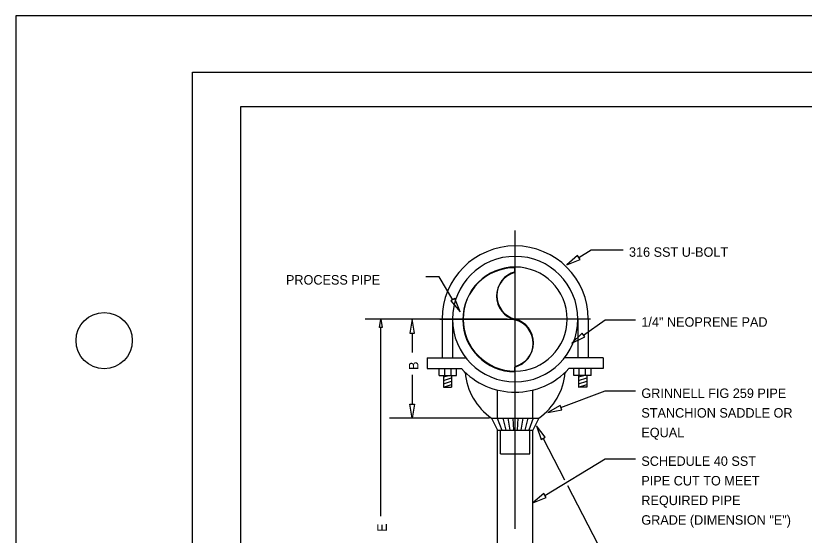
# Model space of a CAD drawing. Extents: x 2147138 to 2147698, y 2147153 to 2147515.
# Drawn here: x 2147137.8 to 2147237.7, y 2147449.2 to 2147515.1 of the extents above; entities that cross this region are included whole.
import ezdxf

# ---------------------------------------------------------------- set-up
doc = ezdxf.new("R2010")
doc.units = 0
for name, color, linetype in [('1', 7, 'Continuous'), ('CONSTRUCTION_CLASS', 7, 'Continuous'), ('G-DETL-ANNO-LW10', 7, 'Continuous'), ('G-DETL-CNTR', 7, 'Continuous'), ('G-DETL-HIDD', 7, 'Continuous'), ('G-DETL-LW10', 7, 'Continuous'), ('G-DETL-PATT', 7, 'Continuous'), ('PATTERN_CLASS', 7, 'Continuous')]:
    doc.layers.add(name, color=color, linetype=linetype)

msp = doc.modelspace()

# ---------------------------------------------------------------- linework, layer by layer
at = {"layer": '1'}
msp.add_line((2147201.099, 2147482.637), (2147201.099, 2147483.237), dxfattribs=at)
at = {"layer": 'CONSTRUCTION_CLASS'}
for p, q in [((2147697.658, 2147515.078), (2147137.785, 2147515.078)), ((2147137.785, 2147515.078), (2147137.785, 2147152.807)), ((2147160.204, 2147507.94), (2147689.056, 2147507.94)), ((2147160.204, 2147160.521), (2147160.204, 2147507.94)), ((2147160.204, 2147507.94), (2147160.204, 2147507.94))]:
    msp.add_line(p, q, dxfattribs=at)
msp.add_circle((2147148.994, 2147473.911), 3.566, dxfattribs=at)
at = {"layer": 'DEFPOINTS'}
for p, q in [((2147201.099, 2147476.637), (2147201.099, 2147476.637)), ((2147198.849, 2147464.074), (2147198.849, 2147464.074))]:
    msp.add_line(p, q, dxfattribs=at)
at = {"layer": 'G-DETL-ANNO-LW10'}
for p, q in [((2147209.173, 2147484.444), (2147210.741, 2147485.424)), ((2147210.741, 2147485.424), (2147214.805, 2147485.424)), ((2147191.481, 2147482.002), (2147189.788, 2147482.002)), ((2147193.202, 2147479.094), (2147191.481, 2147482.002)), ((2147185.7, 2147476.637), (2147182.083, 2147476.637)), ((2147200.099, 2147476.637), (2147185.174, 2147476.637)), ((2147209.759, 2147474.619), (2147212.519, 2147476.56)), ((2147212.519, 2147476.56), (2147216.373, 2147476.56)), ((2147184.06, 2147451.682), (2147184.06, 2147475.583)), ((2147188.054, 2147474.845), (2147188.054, 2147472.399)), ((2147188.054, 2147469.56), (2147188.054, 2147465.866)), ((2147206.912, 2147465.427), (2147212.519, 2147467.53)), ((2147212.519, 2147467.53), (2147216.373, 2147467.53)), ((2147197.849, 2147464.074), (2147185.174, 2147464.074)), ((2147204.651, 2147461.518), (2147207.373, 2147456.272)), ((2147204.881, 2147454.29), (2147212.519, 2147458.929)), ((2147212.519, 2147458.929), (2147216.373, 2147458.929)), ((2147207.743, 2147455.56), (2147212.519, 2147446.356)), ((2147198.849, 2147449.279), (2147198.849, 2147450.771)), ((2147203.349, 2147449.279), (2147203.349, 2147450.771))]:
    msp.add_line(p, q, dxfattribs=at)
for points in [[(2147209.332, 2147484.19), (2147209.015, 2147484.697), (2147207.654, 2147483.494)], [(2147193.459, 2147479.246), (2147192.945, 2147478.942), (2147194.115, 2147477.552)], [(2147183.885, 2147475.583), (2147184.06, 2147476.637), (2147184.236, 2147475.583)], [(2147187.755, 2147474.845), (2147188.353, 2147474.845), (2147188.054, 2147476.637)], [(2147209.931, 2147474.375), (2147209.587, 2147474.863), (2147208.293, 2147473.588)], [(2147187.755, 2147465.866), (2147188.353, 2147465.866), (2147188.054, 2147464.074)], [(2147207.017, 2147465.147), (2147206.808, 2147465.707), (2147205.235, 2147464.798)], [(2147204.386, 2147461.38), (2147204.917, 2147461.655), (2147203.826, 2147463.108)], [(2147205.036, 2147454.035), (2147204.726, 2147454.545), (2147203.349, 2147453.36)]]:
    msp.add_lwpolyline(points, close=True, dxfattribs=at)
at = {"layer": 'G-DETL-CNTR'}
for p, q in [((2147201.099, 2147450.052), (2147201.099, 2147487.863)), ((2147191.558, 2147476.637), (2147201.099, 2147476.637)), ((2147210.64, 2147476.637), (2147201.099, 2147476.637))]:
    msp.add_line(p, q, dxfattribs=at)
at = {"layer": 'G-DETL-HIDD'}
for p, q in [((2147199.224, 2147459.574), (2147199.224, 2147462.574)), ((2147202.974, 2147459.574), (2147202.974, 2147462.574)), ((2147199.224, 2147459.574), (2147202.974, 2147459.574))]:
    msp.add_line(p, q, dxfattribs=at)
at = {"layer": 'G-DETL-LW10'}
for p, q in [((2147191.825, 2147476.637), (2147191.825, 2147471.796)), ((2147193.149, 2147476.637), (2147193.149, 2147471.735)), ((2147209.049, 2147476.637), (2147209.049, 2147471.735)), ((2147210.373, 2147476.637), (2147210.373, 2147471.735)), ((2147189.937, 2147471.735), (2147189.937, 2147470.356)), ((2147189.937, 2147471.735), (2147194.84, 2147471.735)), ((2147212.261, 2147471.735), (2147207.358, 2147471.735)), ((2147212.261, 2147471.735), (2147212.261, 2147470.356)), ((2147189.937, 2147470.356), (2147194.292, 2147470.356)), ((2147191.469, 2147469.504), (2147191.469, 2147470.356)), ((2147192.173, 2147469.504), (2147192.173, 2147470.356)), ((2147192.969, 2147469.504), (2147192.969, 2147470.356)), ((2147193.673, 2147469.504), (2147193.673, 2147470.356)), ((2147212.261, 2147470.356), (2147207.906, 2147470.356)), ((2147208.525, 2147469.504), (2147208.525, 2147470.356)), ((2147209.229, 2147469.504), (2147209.229, 2147470.356)), ((2147210.025, 2147469.504), (2147210.025, 2147470.356)), ((2147210.729, 2147469.504), (2147210.729, 2147470.356)), ((2147191.469, 2147469.504), (2147193.673, 2147469.504)), ((2147192.025, 2147469.301), (2147192.681, 2147469.505)), ((2147192.025, 2147469.504), (2147192.025, 2147468.016)), ((2147192.025, 2147468.872), (2147193.047, 2147469.192)), ((2147193.047, 2147469.504), (2147193.047, 2147468.016)), ((2147210.729, 2147469.504), (2147208.525, 2147469.504)), ((2147209.151, 2147469.301), (2147209.807, 2147469.505)), ((2147209.151, 2147469.504), (2147209.151, 2147468.016)), ((2147209.151, 2147468.872), (2147210.173, 2147469.192)), ((2147210.173, 2147469.504), (2147210.173, 2147468.016)), ((2147192.025, 2147468.444), (2147193.047, 2147468.763)), ((2147192.025, 2147468.016), (2147193.047, 2147468.335)), ((2147209.151, 2147468.444), (2147210.173, 2147468.763)), ((2147209.151, 2147468.016), (2147210.173, 2147468.335)), ((2147192.025, 2147468.016), (2147193.047, 2147468.016)), ((2147198.849, 2147464.074), (2147198.849, 2147467.652)), ((2147203.349, 2147464.074), (2147203.349, 2147467.652)), ((2147210.173, 2147468.016), (2147209.151, 2147468.016)), ((2147198.082, 2147464.074), (2147198.849, 2147462.574)), ((2147198.082, 2147464.074), (2147204.099, 2147464.074)), ((2147198.83, 2147464.074), (2147199.409, 2147462.574)), ((2147199.521, 2147464.074), (2147199.925, 2147462.574)), ((2147200.173, 2147464.074), (2147200.413, 2147462.574)), ((2147200.804, 2147464.074), (2147200.885, 2147462.574)), ((2147201.427, 2147464.074), (2147201.351, 2147462.574)), ((2147202.058, 2147464.074), (2147201.822, 2147462.574)), ((2147202.709, 2147464.074), (2147202.309, 2147462.574)), ((2147203.398, 2147464.074), (2147202.825, 2147462.574)), ((2147204.099, 2147464.074), (2147203.349, 2147462.574)), ((2147198.849, 2147462.574), (2147203.349, 2147462.574)), ((2147198.849, 2147444.832), (2147198.849, 2147462.574)), ((2147203.349, 2147444.832), (2147203.349, 2147462.574))]:
    msp.add_line(p, q, dxfattribs=at)
for centre, radius, start, end in [((2147201.099, 2147476.637), 9.274, 0, 180), ((2147201.099, 2147476.637), 7.95, 0, 180), ((2147201.099, 2147476.637), 6.6, 0, 180), ((2147201.099, 2147476.637), 6.6, 0, 180), ((2147201.099, 2147476.637), 7.95, 180, 360), ((2147201.099, 2147476.637), 6.6, 180, 0), ((2147201.099, 2147476.637), 9.262, 222.69828, 317.30172), ((2147202.623, 2147470.53), 7.883, 184.75423, 234.97861), ((2147199.575, 2147470.53), 7.883, 305.02139, 355.24577)]:
    msp.add_arc(centre, radius, start, end, dxfattribs=at)
at = {"layer": 'G-DETL-PATT'}
for points in [[(2147201.072, 2147482.55), (2147201.072, 2147483.15)], [(2147201.072, 2147469.95), (2147201.072, 2147470.565)]]:
    msp.add_lwpolyline(points, dxfattribs=at)
for centre, radius, start, end in [((2147201.072, 2147476.55), 6.6, 90, 270), ((2147201.841, 2147479.55), 3.097, 104.3818, 255.6182), ((2147201.868, 2147479.637), 3.097, 104.3818, 255.6182), ((2147200.332, 2147473.645), 3.089, 283.20998, 75.6182), ((2147200.304, 2147473.558), 3.089, 284.3818, 75.6182)]:
    msp.add_arc(centre, radius, start, end, dxfattribs=at)
at = {"layer": 'PATTERN_CLASS'}
for p, q in [((2147290.476, 2147503.536), (2147166.29, 2147503.536)), ((2147166.29, 2147503.536), (2147166.29, 2147351.266))]:
    msp.add_line(p, q, dxfattribs=at)

# ---------------------------------------------------------------- texts
at = {"layer": 'G-DETL-ANNO-LW10'}
for s, p in [('316 SST U-BOLT', (2147215.531, 2147484.535)), ('PROCESS PIPE', (2147172.041, 2147481.011)), ('1/4" NEOPRENE PAD', (2147217.099, 2147475.671)), ('GRINNELL FIG 259 PIPE', (2147217.099, 2147466.641)), ('STANCHION SADDLE OR', (2147217.099, 2147464.154)), ('EQUAL', (2147217.099, 2147461.667)), ('SCHEDULE 40 SST', (2147217.099, 2147458.04)), ('PIPE CUT TO MEET', (2147217.099, 2147455.554)), ('REQUIRED PIPE', (2147217.099, 2147453.067)), ('GRADE (DIMENSION "E")', (2147217.099, 2147450.58))]:
    msp.add_text(s, height=1.2, dxfattribs=at).set_placement(p)
for s, p in [('B', (2147188.824, 2147470.186)), ('E', (2147184.835, 2147449.676))]:
    msp.add_text(s, height=1.2, rotation=90, dxfattribs=at).set_placement(p)

doc.saveas('drawing.dxf')
